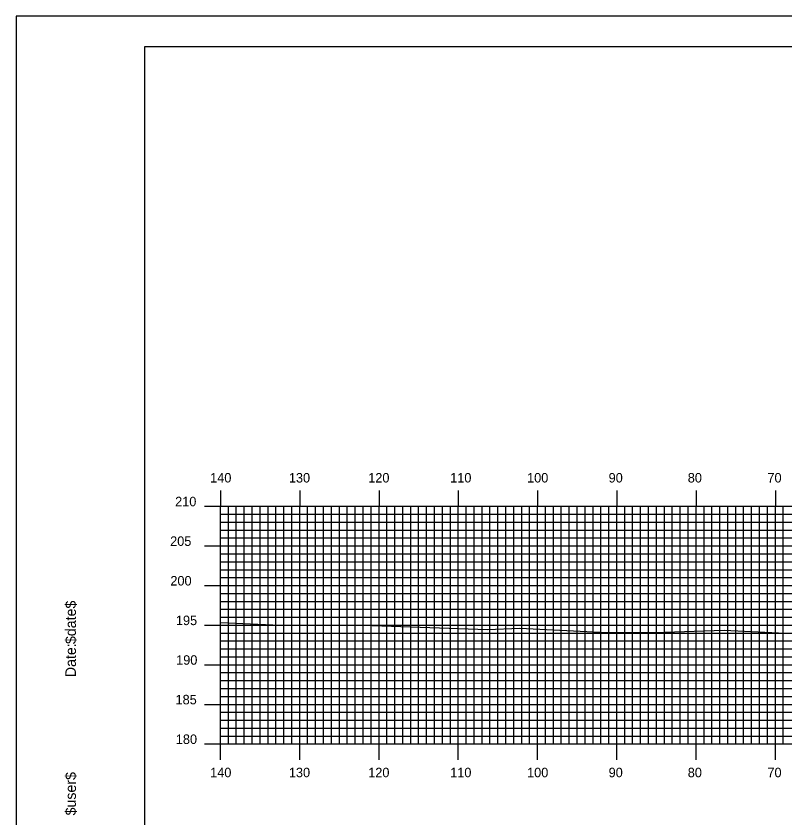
# Model space of a CAD drawing. Extents: x 1807045 to 1807388, y 442591 to 442811.
# Drawn here: x 1807045 to 1807142, y 442709.3 to 442810.5 of the extents above; entities that cross this region are included whole.
import ezdxf

# ---------------------------------------------------------------- set-up
doc = ezdxf.new("R2010")
doc.units = 0
for name, color, linetype in [('BORDER', 7, 'Continuous'), ('H_V ANNOTATION', 7, 'Continuous'), ('MAJOR', 7, 'Continuous'), ('MINOR', 7, 'Continuous'), ('PLOT BOUNDARY', 7, 'Continuous'), ('S_Roadway_Centerline', 7, 'Continuous')]:
    doc.layers.add(name, color=color, linetype=linetype)

msp = doc.modelspace()

# ---------------------------------------------------------------- linework, layer by layer
at = {"layer": 'BORDER'}
msp.add_lwpolyline([(1807061.16, 442596.67), (1807381.16, 442596.67), (1807381.16, 442806.67), (1807061.16, 442806.67)], close=True, dxfattribs=at)
at = {"layer": 'MAJOR'}
for p, q in [((1807070.76, 442750.67), (1807070.76, 442748.67)), ((1807080.76, 442750.67), (1807080.76, 442748.67)), ((1807090.76, 442750.67), (1807090.76, 442748.67)), ((1807100.76, 442750.67), (1807100.76, 442748.67)), ((1807110.76, 442750.67), (1807110.76, 442748.67)), ((1807120.76, 442750.67), (1807120.76, 442748.67)), ((1807130.76, 442750.67), (1807130.76, 442748.67)), ((1807140.76, 442750.67), (1807140.76, 442748.67)), ((1807068.75, 442748.67), (1807070.76, 442748.67)), ((1807070.76, 442748.67), (1807350.76, 442748.67)), ((1807070.76, 442718.67), (1807070.76, 442748.67)), ((1807070.76, 442718.67), (1807070.76, 442748.67)), ((1807070.76, 442748.67), (1807350.76, 442748.67)), ((1807080.76, 442718.67), (1807080.76, 442748.67)), ((1807090.76, 442718.67), (1807090.76, 442748.67)), ((1807100.76, 442718.67), (1807100.76, 442748.67)), ((1807110.76, 442718.67), (1807110.76, 442748.67)), ((1807120.76, 442718.67), (1807120.76, 442748.67)), ((1807130.76, 442718.67), (1807130.76, 442748.67)), ((1807140.76, 442718.67), (1807140.76, 442748.67)), ((1807068.75, 442743.67), (1807070.76, 442743.67)), ((1807070.76, 442743.67), (1807350.76, 442743.67)), ((1807068.75, 442738.67), (1807070.76, 442738.67)), ((1807070.76, 442738.67), (1807350.76, 442738.67)), ((1807068.75, 442733.67), (1807070.76, 442733.67)), ((1807070.76, 442733.67), (1807350.76, 442733.67)), ((1807068.75, 442728.67), (1807070.76, 442728.67)), ((1807070.76, 442728.67), (1807350.76, 442728.67)), ((1807068.75, 442723.67), (1807070.76, 442723.67)), ((1807070.76, 442723.67), (1807350.76, 442723.67)), ((1807068.75, 442718.67), (1807070.76, 442718.67)), ((1807070.76, 442718.67), (1807350.76, 442718.67)), ((1807070.76, 442718.67), (1807350.76, 442718.67)), ((1807070.76, 442716.66), (1807070.76, 442718.67)), ((1807080.76, 442716.66), (1807080.76, 442718.67)), ((1807090.76, 442716.66), (1807090.76, 442718.67)), ((1807100.76, 442716.66), (1807100.76, 442718.67)), ((1807110.76, 442716.66), (1807110.76, 442718.67)), ((1807120.76, 442716.66), (1807120.76, 442718.67)), ((1807130.76, 442716.66), (1807130.76, 442718.67)), ((1807140.76, 442716.66), (1807140.76, 442718.67))]:
    msp.add_line(p, q, dxfattribs=at)
at = {"layer": 'MINOR'}
for p, q in [((1807071.76, 442718.67), (1807071.76, 442748.67)), ((1807072.76, 442718.67), (1807072.76, 442748.67)), ((1807073.76, 442718.67), (1807073.76, 442748.67)), ((1807074.76, 442718.67), (1807074.76, 442748.67)), ((1807075.76, 442718.67), (1807075.76, 442748.67)), ((1807076.76, 442718.67), (1807076.76, 442748.67)), ((1807077.76, 442718.67), (1807077.76, 442748.67)), ((1807078.76, 442718.67), (1807078.76, 442748.67)), ((1807079.76, 442718.67), (1807079.76, 442748.67)), ((1807081.76, 442718.67), (1807081.76, 442748.67)), ((1807082.76, 442718.67), (1807082.76, 442748.67)), ((1807083.76, 442718.67), (1807083.76, 442748.67)), ((1807084.76, 442718.67), (1807084.76, 442748.67)), ((1807085.76, 442718.67), (1807085.76, 442748.67)), ((1807086.76, 442718.67), (1807086.76, 442748.67)), ((1807087.76, 442718.67), (1807087.76, 442748.67)), ((1807088.76, 442718.67), (1807088.76, 442748.67)), ((1807089.76, 442718.67), (1807089.76, 442748.67)), ((1807091.76, 442718.67), (1807091.76, 442748.67)), ((1807092.76, 442718.67), (1807092.76, 442748.67)), ((1807093.76, 442718.67), (1807093.76, 442748.67)), ((1807094.76, 442718.67), (1807094.76, 442748.67)), ((1807095.76, 442718.67), (1807095.76, 442748.67)), ((1807096.76, 442718.67), (1807096.76, 442748.67)), ((1807097.76, 442718.67), (1807097.76, 442748.67)), ((1807098.76, 442718.67), (1807098.76, 442748.67)), ((1807099.76, 442718.67), (1807099.76, 442748.67)), ((1807101.76, 442718.67), (1807101.76, 442748.67)), ((1807102.76, 442718.67), (1807102.76, 442748.67)), ((1807103.76, 442718.67), (1807103.76, 442748.67)), ((1807104.76, 442718.67), (1807104.76, 442748.67)), ((1807105.76, 442718.67), (1807105.76, 442748.67)), ((1807106.76, 442718.67), (1807106.76, 442748.67)), ((1807107.76, 442718.67), (1807107.76, 442748.67)), ((1807108.76, 442718.67), (1807108.76, 442748.67)), ((1807109.76, 442718.67), (1807109.76, 442748.67)), ((1807111.76, 442718.67), (1807111.76, 442748.67)), ((1807112.76, 442718.67), (1807112.76, 442748.67)), ((1807113.76, 442718.67), (1807113.76, 442748.67)), ((1807114.76, 442718.67), (1807114.76, 442748.67)), ((1807115.76, 442718.67), (1807115.76, 442748.67)), ((1807116.76, 442718.67), (1807116.76, 442748.67)), ((1807117.76, 442718.67), (1807117.76, 442748.67)), ((1807118.76, 442718.67), (1807118.76, 442748.67)), ((1807119.76, 442718.67), (1807119.76, 442748.67)), ((1807121.76, 442718.67), (1807121.76, 442748.67)), ((1807122.76, 442718.67), (1807122.76, 442748.67)), ((1807123.76, 442718.67), (1807123.76, 442748.67)), ((1807124.76, 442718.67), (1807124.76, 442748.67)), ((1807125.76, 442718.67), (1807125.76, 442748.67)), ((1807126.76, 442718.67), (1807126.76, 442748.67)), ((1807127.76, 442718.67), (1807127.76, 442748.67)), ((1807128.76, 442718.67), (1807128.76, 442748.67)), ((1807129.76, 442718.67), (1807129.76, 442748.67)), ((1807131.76, 442718.67), (1807131.76, 442748.67)), ((1807132.76, 442718.67), (1807132.76, 442748.67)), ((1807133.76, 442718.67), (1807133.76, 442748.67)), ((1807134.76, 442718.67), (1807134.76, 442748.67)), ((1807135.76, 442718.67), (1807135.76, 442748.67)), ((1807136.76, 442718.67), (1807136.76, 442748.67)), ((1807137.76, 442718.67), (1807137.76, 442748.67)), ((1807138.76, 442718.67), (1807138.76, 442748.67)), ((1807139.76, 442718.67), (1807139.76, 442748.67)), ((1807141.76, 442718.67), (1807141.76, 442748.67)), ((1807070.76, 442747.67), (1807350.76, 442747.67)), ((1807070.76, 442747.67), (1807072.76, 442747.67)), ((1807070.76, 442746.67), (1807350.76, 442746.67)), ((1807070.76, 442746.67), (1807072.76, 442746.67)), ((1807070.76, 442745.67), (1807350.76, 442745.67)), ((1807070.76, 442745.67), (1807072.76, 442745.67)), ((1807070.76, 442744.67), (1807350.76, 442744.67)), ((1807070.76, 442744.67), (1807072.76, 442744.67)), ((1807070.76, 442742.67), (1807350.76, 442742.67)), ((1807070.76, 442742.67), (1807072.76, 442742.67)), ((1807070.76, 442741.67), (1807350.76, 442741.67)), ((1807070.76, 442741.67), (1807072.76, 442741.67)), ((1807070.76, 442740.67), (1807350.76, 442740.67)), ((1807070.76, 442740.67), (1807072.76, 442740.67)), ((1807070.76, 442739.67), (1807350.76, 442739.67)), ((1807070.76, 442739.67), (1807072.76, 442739.67)), ((1807070.76, 442737.67), (1807350.76, 442737.67)), ((1807070.76, 442737.67), (1807072.76, 442737.67)), ((1807070.76, 442736.67), (1807350.76, 442736.67)), ((1807070.76, 442736.67), (1807072.76, 442736.67)), ((1807070.76, 442735.67), (1807350.76, 442735.67)), ((1807070.76, 442735.67), (1807072.76, 442735.67)), ((1807070.76, 442734.67), (1807350.76, 442734.67)), ((1807070.76, 442734.67), (1807072.76, 442734.67)), ((1807070.76, 442732.67), (1807350.76, 442732.67)), ((1807070.76, 442732.67), (1807072.76, 442732.67)), ((1807070.76, 442731.67), (1807350.76, 442731.67)), ((1807070.76, 442731.67), (1807072.76, 442731.67)), ((1807070.76, 442730.67), (1807350.76, 442730.67)), ((1807070.76, 442730.67), (1807072.76, 442730.67)), ((1807070.76, 442729.67), (1807350.76, 442729.67)), ((1807070.76, 442729.67), (1807072.76, 442729.67)), ((1807070.76, 442727.67), (1807350.76, 442727.67)), ((1807070.76, 442727.67), (1807072.76, 442727.67)), ((1807070.76, 442726.67), (1807350.76, 442726.67)), ((1807070.76, 442726.67), (1807072.76, 442726.67)), ((1807070.76, 442725.67), (1807350.76, 442725.67)), ((1807070.76, 442725.67), (1807072.76, 442725.67)), ((1807070.76, 442724.67), (1807350.76, 442724.67)), ((1807070.76, 442724.67), (1807072.76, 442724.67)), ((1807070.76, 442722.67), (1807350.76, 442722.67)), ((1807070.76, 442722.67), (1807072.76, 442722.67)), ((1807070.76, 442721.67), (1807350.76, 442721.67)), ((1807070.76, 442721.67), (1807072.76, 442721.67)), ((1807070.76, 442720.67), (1807350.76, 442720.67)), ((1807070.76, 442720.67), (1807072.76, 442720.67)), ((1807070.76, 442719.67), (1807350.76, 442719.67)), ((1807070.76, 442719.67), (1807072.76, 442719.67))]:
    msp.add_line(p, q, dxfattribs=at)
at = {"layer": 'PLOT BOUNDARY'}
msp.add_lwpolyline([(1807044.97, 442590.55), (1807384.97, 442590.55), (1807384.97, 442810.55), (1807044.97, 442810.55)], close=True, dxfattribs=at)
at = {"layer": 'S_Roadway_Centerline'}
msp.add_lwpolyline([(1807070.76, 442734), (1807077.35, 442733.71), (1807083.9, 442733.68), (1807088.67, 442733.68), (1807104.46, 442733.12), (1807108.52, 442733.27), (1807119.52, 442732.72), (1807125.53, 442732.76), (1807134.32, 442733.04), (1807145.45, 442732.49), (1807158.42, 442732.06), (1807167.83, 442731.58), (1807170.31, 442731.53), (1807173.41, 442731.52), (1807186.45, 442731.49), (1807198.87, 442731.18), (1807223.95, 442731.18), (1807228.51, 442731.27), (1807248.47, 442731.22), (1807250.1, 442731.17), (1807252.52, 442731.12), (1807263.1, 442731.07), (1807274.86, 442730.25)], dxfattribs=at)

# ---------------------------------------------------------------- texts
at = {"layer": 'BORDER'}
for s, p in [('$date$', (1807052.53, 442731.28)), ('Date:', (1807052.53, 442727.1)), ('$user$', (1807052.53, 442709.65))]:
    msp.add_text(s, height=1.339, rotation=90, dxfattribs=at).set_placement(p)
at = {"layer": 'H_V ANNOTATION'}
for s, p in [('140', (1807069.46, 442751.67)), ('130', (1807079.39, 442751.67)), ('120', (1807089.4, 442751.67)), ('110', (1807099.74, 442751.67)), ('100', (1807109.44, 442751.67)), ('90', (1807119.73, 442751.67)), ('80', (1807129.71, 442751.67)), ('70', (1807139.76, 442751.67)), ('210', (1807065.04, 442748.67)), ('205', (1807064.41, 442743.67)), ('200', (1807064.44, 442738.67)), ('195', (1807065.14, 442733.67)), ('190', (1807065.17, 442728.67)), ('185', (1807065.09, 442723.67)), ('180', (1807065.13, 442718.67)), ('140', (1807069.46, 442714.47)), ('130', (1807079.39, 442714.47)), ('120', (1807089.4, 442714.47)), ('110', (1807099.74, 442714.47)), ('100', (1807109.44, 442714.47)), ('90', (1807119.73, 442714.47)), ('80', (1807129.71, 442714.47)), ('70', (1807139.76, 442714.47))]:
    msp.add_text(s, height=1.2, dxfattribs=at).set_placement(p)
at = {"layer": 'MAJOR'}
msp.add_text('-', height=0.012, dxfattribs=at).set_placement((1807070.75, 442718.67))

doc.saveas('drawing.dxf')
